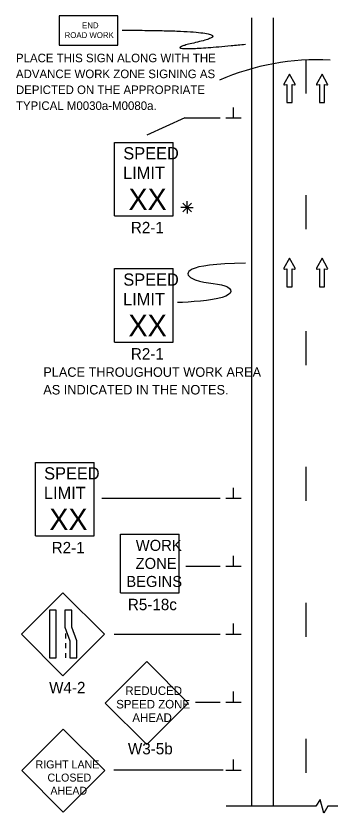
# Model space of a CAD drawing. Extents: x 16740 to 18479, y 5932 to 6964.
# Drawn here: x 16740 to 16971, y 6342 to 6928 of the extents above; entities that cross this region are included whole.
import ezdxf

# ---------------------------------------------------------------- set-up
doc = ezdxf.new("R2010")
doc.units = 0
for name, color, linetype in [('ALI_LEGAL_EX', 7, 'Continuous'), ('MT_SCRATCH_LEVEL_E', 7, 'Continuous'), ('PAVT_EDGE_EX', 7, 'Continuous'), ('TRAFFIC_SIGNS_PR', 7, 'Continuous'), ('TYPICAL_TEXT_DIMEN_PR', 7, 'Continuous')]:
    doc.layers.add(name, color=color, linetype=linetype)

msp = doc.modelspace()

# ---------------------------------------------------------------- linework, layer by layer
at = {"layer": 'ALI_LEGAL_EX'}
for points in [[(16952.72, 6896.22), (16952.72, 6871.22)], [(16952.72, 6796.22), (16952.72, 6771.22)], [(16952.72, 6696.22), (16952.72, 6671.22)], [(16952.72, 6596.22), (16952.72, 6571.22)], [(16952.72, 6496.22), (16952.72, 6471.22)], [(16952.72, 6396.22), (16952.72, 6371.22)]]:
    msp.add_lwpolyline(points, dxfattribs=at)
at = {"layer": 'MT_SCRATCH_LEVEL_E'}
for p, q in [((16940.72, 6885.31), (16936.61, 6878.07)), ((16944.87, 6878.07), (16940.72, 6885.31)), ((16964.62, 6885.31), (16960.51, 6878.07)), ((16968.77, 6878.07), (16964.62, 6885.31)), ((16937.09, 6877.38), (16938.87, 6877.7)), ((16938.87, 6877.7), (16938.87, 6864.44)), ((16942.61, 6864.44), (16942.61, 6877.7)), ((16942.61, 6877.7), (16944.39, 6877.38)), ((16960.99, 6877.38), (16962.77, 6877.7)), ((16962.77, 6877.7), (16962.77, 6864.44)), ((16966.51, 6864.44), (16966.51, 6877.7)), ((16966.51, 6877.7), (16968.29, 6877.38)), ((16938.87, 6864.44), (16942.61, 6864.44)), ((16962.77, 6864.44), (16966.51, 6864.44)), ((16940.72, 6749.79), (16936.61, 6742.55)), ((16944.87, 6742.55), (16940.72, 6749.79)), ((16964.62, 6749.79), (16960.51, 6742.55)), ((16968.77, 6742.55), (16964.62, 6749.79)), ((16937.09, 6741.86), (16938.87, 6742.18)), ((16938.87, 6742.18), (16938.87, 6728.92)), ((16942.61, 6728.92), (16942.61, 6742.18)), ((16942.61, 6742.18), (16944.39, 6741.86)), ((16960.99, 6741.86), (16962.77, 6742.18)), ((16962.77, 6742.18), (16962.77, 6728.92)), ((16966.51, 6728.92), (16966.51, 6742.18)), ((16966.51, 6742.18), (16968.29, 6741.86)), ((16938.87, 6728.92), (16942.61, 6728.92)), ((16962.77, 6728.92), (16966.51, 6728.92))]:
    msp.add_line(p, q, dxfattribs=at)
for centre, start, end in [((16937.02, 6877.84), 150.42484, 279.96381), ((16944.46, 6877.84), 260.03619, 29.77312), ((16960.92, 6877.84), 150.42484, 279.96381), ((16968.36, 6877.84), 260.03619, 29.77312), ((16937.02, 6742.32), 150.42484, 279.96381), ((16944.46, 6742.32), 260.03619, 29.77312), ((16960.92, 6742.32), 150.42484, 279.96381), ((16968.36, 6742.32), 260.03619, 29.77312)]:
    msp.add_arc(centre, 0.463, start, end, dxfattribs=at)
at = {"layer": 'PAVT_EDGE_EX'}
for p, q in [((16912.72, 6926.76), (16912.72, 6346.64)), ((16928.72, 6926.76), (16928.72, 6346.64))]:
    msp.add_line(p, q, dxfattribs=at)
at = {"layer": 'TRAFFIC_SIGNS_PR'}
for p, q in [((16812.01, 6835.14), (16855.21, 6835.14)), ((16812.01, 6781.14), (16812.01, 6835.14)), ((16855.21, 6781.14), (16855.21, 6835.14)), ((16812.01, 6781.14), (16855.21, 6781.14)), ((16812.01, 6742.19), (16855.21, 6742.19)), ((16812.01, 6688.19), (16812.01, 6742.19)), ((16855.21, 6688.19), (16855.21, 6742.19)), ((16812.01, 6688.19), (16855.21, 6688.19)), ((16753.78, 6599.56), (16796.98, 6599.56)), ((16753.78, 6545.56), (16753.78, 6599.56)), ((16796.98, 6545.56), (16796.98, 6599.56)), ((16753.78, 6545.56), (16796.98, 6545.56)), ((16816.41, 6503.68), (16816.41, 6546.88)), ((16816.41, 6546.88), (16859.61, 6546.88)), ((16859.61, 6503.68), (16859.61, 6546.88)), ((16774.08, 6503.66), (16743.54, 6473.11)), ((16804.63, 6473.11), (16774.08, 6503.66)), ((16816.41, 6503.68), (16859.61, 6503.68)), ((16743.54, 6473.11), (16774.08, 6442.56)), ((16774.08, 6442.56), (16804.63, 6473.11)), ((16775.93, 6473.66), (16775.93, 6470.06)), ((16775.93, 6466.46), (16775.93, 6462.86)), ((16775.93, 6459.26), (16775.93, 6455.66)), ((16835.71, 6452.96), (16805.16, 6422.41)), ((16866.25, 6422.41), (16835.71, 6452.96)), ((16805.16, 6422.41), (16835.71, 6391.86)), ((16835.71, 6391.86), (16866.25, 6422.41)), ((16774.28, 6403.35), (16743.73, 6372.8)), ((16804.83, 6372.8), (16774.28, 6403.35)), ((16743.73, 6372.8), (16774.28, 6342.25)), ((16774.28, 6342.25), (16804.83, 6372.8))]:
    msp.add_line(p, q, dxfattribs=at)
for points in [[(16771.26, 6906.59), (16814.46, 6906.59), (16814.46, 6928.19), (16771.26, 6928.19)], [(16764.08, 6490.81), (16764.08, 6455.66), (16769.13, 6455.66), (16769.13, 6490.81)], [(16775.48, 6490.81), (16775.48, 6478.23), (16779.24, 6468.24), (16779.24, 6455.66), (16784.3, 6455.66), (16784.3, 6468.24), (16780.53, 6478.23), (16780.53, 6490.81)]]:
    msp.add_lwpolyline(points, close=True, dxfattribs=at)
msp.add_arc((16961.52, 6713.48), 182.45, 87.16713, 113.38058, dxfattribs=at)
msp.add_open_spline([(16817.69, 6917.66), (16911.43, 6917.66), (16834.91, 6900.25), (16908.24, 6907.32)], degree=2, dxfattribs=at)
at = {"layer": 'TYPICAL_TEXT_DIMEN_PR'}
for p, q in [((16899.6, 6853.12), (16899.6, 6860.91)), ((16863.72, 6853.12), (16835.83, 6840.44)), ((16863.72, 6853.12), (16889.72, 6853.12)), ((16893.97, 6853.12), (16905.22, 6853.12)), ((16862.22, 6790.49), (16868.59, 6784.11)), ((16868.59, 6790.49), (16862.22, 6784.11)), ((16865.4, 6787.3), (16865.4, 6791.76)), ((16865.4, 6787.3), (16860.87, 6787.3)), ((16865.4, 6787.3), (16868.59, 6787.3)), ((16865.4, 6787.3), (16869.88, 6787.3)), ((16865.4, 6787.3), (16865.4, 6782.8)), ((16899.6, 6573.15), (16899.6, 6580.93)), ((16802.72, 6573.15), (16889.72, 6573.15)), ((16893.97, 6573.15), (16905.22, 6573.15)), ((16899.6, 6523.15), (16899.6, 6530.93)), ((16864.47, 6523.15), (16889.72, 6523.15)), ((16893.97, 6523.15), (16905.22, 6523.15)), ((16899.6, 6473.15), (16899.6, 6480.93)), ((16811.84, 6473.15), (16889.72, 6473.15)), ((16893.97, 6473.15), (16905.22, 6473.15)), ((16899.6, 6423.15), (16899.6, 6430.93)), ((16871.56, 6423.15), (16889.72, 6423.15)), ((16893.97, 6423.15), (16905.22, 6423.15)), ((16899.6, 6373.15), (16899.6, 6380.93)), ((16891.81, 6373.15), (16811.45, 6373.15)), ((16893.97, 6373.15), (16905.22, 6373.15)), ((16963.32, 6351.44), (16960.07, 6346.64)), ((16966.07, 6341.5), (16963.32, 6351.44)), ((16960.07, 6346.64), (16894.13, 6346.64)), ((16968.81, 6346.64), (16966.07, 6341.5)), ((17031.14, 6346.64), (16968.81, 6346.64))]:
    msp.add_line(p, q, dxfattribs=at)
msp.add_open_spline([(16908.35, 6746.23), (16862.49, 6745.71), (16862.94, 6731.56), (16899.23, 6731.56), (16899.23, 6719.44), (16867.27, 6717.54), (16858.39, 6717.22)], degree=3, dxfattribs=at)

# ---------------------------------------------------------------- texts
at = {"layer": 'TRAFFIC_SIGNS_PR'}
for s, height, p in [('END', 4.31, (16788.14, 6919.11)), ('ROAD WORK', 4.31, (16775.32, 6911.92)), ('PLACE THIS SIGN ALONG WITH THE', 6.3, (16739.51, 6894.1)), ('ADVANCE WORK ZONE SIGNING AS', 6.3, (16739.51, 6882.4)), ('DEPICTED ON THE APPROPRIATE', 6.3, (16739.51, 6870.7)), ('TYPICAL M0030a-M0080a.', 6.3, (16739.51, 6859)), ('SPEED', 9, (16818.5, 6822.61)), ('LIMIT', 9, (16818.31, 6808.21)), ('XX', 15.785, (16822.26, 6785.37)), ('R2-1', 8.37, (16824.02, 6768.27)), ('SPEED', 9, (16818.5, 6729.66)), ('LIMIT', 9, (16818.31, 6715.26)), ('XX', 15.785, (16822.26, 6692.42)), ('R2-1', 8.37, (16824.02, 6675.32)), ('PLACE THROUGHOUT WORK AREA', 7, (16759.63, 6662.57)), ('AS INDICATED IN THE NOTES.', 7, (16759.63, 6649.57)), ('SPEED', 9, (16760.27, 6587.02)), ('LIMIT', 9, (16760.09, 6572.62)), ('XX', 15.785, (16764.04, 6549.78)), ('WORK', 8.119, (16827.66, 6534.47)), ('R2-1', 8.37, (16765.79, 6532.69)), ('ZONE', 8.119, (16827.53, 6521.19)), ('BEGINS', 8.119, (16820.7, 6507.9)), ('R5-18c', 8.37, (16821.82, 6490.82)), ('W4-2', 8.37, (16763.91, 6429.69)), ('REDUCED', 6.3, (16820.02, 6428.38)), ('SPEED ZONE', 6.3, (16813.26, 6418.48)), ('AHEAD', 6.3, (16825.14, 6408.58)), ('W3-5b', 8.37, (16821.87, 6384.71)), ('RIGHT LANE', 5.85, (16753.94, 6374.37)), ('CLOSED', 5.85, (16762.71, 6364.7)), ('AHEAD', 5.85, (16764.89, 6355.02))]:
    msp.add_text(s, height=height, dxfattribs=at).set_placement(p)

doc.saveas('drawing.dxf')
